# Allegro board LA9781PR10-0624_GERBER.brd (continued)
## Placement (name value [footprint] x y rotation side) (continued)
R775  -  [R_0402]  226.97 72.45 0 bottom
R779  -  [R_0402]  247.06 65.34 180 bottom
R781  -  [R_0402]  41.57 68.66 180 top
R782  -  [R_0402]  238.73 61.48 270 bottom
R783  -  [R_0402]  21.61 166.69 0 top
R793  -  [R_0402]  246.15 69.66 0 bottom
R794  -  [R_0402]  233.78 61.48 270 bottom
R795  -  [R_0402]  236.7 61.48 270 bottom
R796  -  [R_0402]  27.76 23.1 270 top
R797  -  [R0402_0OHM]  226.97 73.34 0 bottom
R799  -  [R_0402]  35.48 84.77 180 bottom
R800  -  [R_0402]  237.72 80.53 270 bottom
R801  -  [R_0603]  289.47 133.29 0 top
R802  -  [R0402_0OHM]  244.96 60.57 90 bottom
R803  -  [R_0402]  238.61 79.62 90 bottom
R804  -  [R_0402]  244.07 61.48 270 bottom
R805  -  [R_0402]  232.38 78.25 270 bottom
R806  -  [R0402_0OHM]  98.2 37.91 0 top
R807  -  [R_0402]  233.27 78.25 270 bottom
R808  -  [R_0402]  63.14 57.86 0 bottom
R809  -  [R_0402]  271.63 69.48 270 bottom
R810  -  [R_0402]  236.19 37.1 270 bottom
R811  -  [R_0402]  236.19 34.94 270 bottom
R812  -  [R_0402]  252.02 45.02 180 bottom
R814  -  [R_0402]  254.3 45.91 180 bottom
R815  -  [R_0402]  104.42 165.27 180 top
R816  -  [R_0402]  293.6 61.23 270 bottom
R817  -  [R_0402]  240 57.29 270 bottom
R819  -  [R_0402]  236.4 38.47 90 bottom
R822  -  [R_0402]  234.47 44.77 0 bottom
R823  -  [R_0402]  128.24 170.04 90 bottom
R824  -  [R_0402]  129.54 157.34 270 bottom
R825  -  [R_0402]  234.29 39.38 270 bottom
R827  -  [R0402_0OHM]  4.04 144.89 90 bottom
R828  -  [R0402_0OHM]  4.93 144.89 90 bottom
R829  -  [R_0402]  233.09 44.77 180 bottom
R830  -  [R0402_0OHM]  275.64 75.5 180 bottom
R831  -  [R0402_0OHM]  275.64 74.61 180 bottom
R834  -  [R0402_0OHM]  237.34 55 270 bottom
R835  -  [R_0402]  247.55 37.33 90 bottom
R836  -  [R_0402]  245.72 38.24 270 bottom
R837  -  [R_0402]  238.23 55 270 bottom
R838  -  [R_0402]  234.48 42.36 0 bottom
R839  -  [R0402_0OHM]  104.42 164.39 180 top
R840  -  [R_0402]  2.04 150.18 90 bottom
R841  -  [R_0402]  233.09 42.36 180 bottom
R842  -  [R0402_0OHM]  6.32 144.89 90 bottom
R843  -  [R_0402]  253.52 50.86 0 bottom
R844  -  [R0402_0OHM]  7.21 144.89 90 bottom
R845  -  [R0402_0OHM]  244.83 37.33 90 bottom
R846  -  [R0402_0OHM]  232.05 51.5 0 bottom
R847  -  [R_0402]  272.9 30.54 0 bottom
R848  -  [R_0402]  270.89 30.29 180 bottom
R849  -  [R_0402]  272.9 28.51 0 bottom
R850  -  [R_0402]  272.9 29.53 0 bottom
R851  -  [R_0402]  3.41 150.19 90 bottom
R852  -  [R_0402]  3.41 149.29 270 bottom
R853  -  [R_0402]  2.04 149.29 270 bottom
R858  -  [R_0402]  272.9 34.61 0 bottom
R859  -  [R_0402]  272.9 33.59 0 bottom
R860  -  [R_0402]  272.9 32.58 0 bottom
R861  -  [R_0402]  272.9 31.56 0 bottom
R864  -  [R_0402]  272.9 35.62 0 bottom
R866  -  [R0402_0OHM]  250.98 39.18 0 bottom
R869  -  [R_0402]  251.89 46.93 180 bottom
R870  -  [R_0402]  243.05 34.79 90 bottom
R871  -  [R_0402]  234.47 45.66 0 bottom
R872  -  [R_0402]  233.21 36.18 90 bottom
R874  -  [R_0402]  241.27 35.7 270 bottom
R875  -  [R_0402]  233.09 45.66 180 bottom
R876  -  [R_0402]  242.16 35.7 270 bottom
R877  -  [R_0402]  98.19 40.7 0 top
R878  -  [R0402_0OHM]  98.19 39.82 0 top
R879  -  [R_0402]  234.16 36.18 90 bottom
R880  -  [R_0402]  234.47 40.5 0 bottom
R884  -  [R_0402]  233.09 41.42 180 bottom
R885  -  [R_0402]  246.68 55.44 180 bottom
R887  -  [R_0402]  245.72 35.7 270 bottom
R889  -  [R_0402]  251.76 50.86 180 bottom
R892  -  [R_0402]  253.39 46.93 0 bottom
R893  -  [R_0402]  255.67 50.86 0 bottom
R895  -  [R_0402]  114.73 61.41 180 bottom
R897  -  [R_0402]  101.65 59.37 180 bottom
R899  -  [R_0402]  101.65 66.61 180 bottom
R900  -  [R_0402]  101.65 56.71 180 bottom
R901  -  [R_0402]  101.65 63.95 180 bottom
R904  -  [R_0402]  294.99 109.08 90 bottom
R909  -  [R_0402]  38.45 72.5 90 top
R925  -  [R_0402]  46.96 75.17 90 top
R930  -  [R_0402]  40.99 76.09 270 top
R931  -  [R_0402]  44.68 75.17 90 top
R932  -  [R_0402]  35.46 87.06 0 top
R933  -  [R_0402]  39.6 76.09 270 top
R934  -  [R_0402]  26.26 85.23 270 top
R935  -  [R_0402]  25.88 130.44 270 top
R936  -  [R_0402]  114.73 62.29 180 bottom
R937  -  [R_0402]  129.77 168.03 270 top
R938  -  [R_0402]  290.84 103.39 90 bottom
R939  -  [R_0402]  133.75 169.99 0 top
R940  -  [R_0402]  13.36 134.05 0 top
R941  -  [R_0402]  291.86 104.31 270 bottom
R942  -  [R_0402]  22.66 76.52 180 top
R943  -  [R_0402]  29.01 82.74 180 top
R944  -  [R_0402]  15.2 134.18 0 top
R952  -  [R_0402]  256.69 39.94 0 bottom
R955  -  [R_0402]  284.83 88.66 270 top
R956  -  [R_0402]  284.83 89.52 90 top
R1068  -  [R0402_0OHM]  238.3 37.91 180 bottom
R1069  -  [R_0402]  243.13 57.34 180 bottom
R1118  -  [R_0402]  247.5 35.7 270 bottom
R1121  -  [R_0402]  91.41 155.84 270 bottom
R1122  -  [R_0402]  87.1 148.91 90 top
R1123  -  [R_0402]  92.3 155.84 270 bottom
R1124  -  [R_0402]  88.17 152.59 180 top
R1125  -  [R_0402]  232.38 38.47 90 bottom
R1126  -  [R_0402]  252.02 42.74 180 bottom
R1128  -  [R_0402]  42.01 163.31 90 top
R1133  -  [R_0402]  297.45 112.42 0 bottom
R1134  -  [R_0402]  297.46 111.52 0 bottom
R1137  -  [R_0402]  95.86 167.96 270 bottom
R1138  -  [R_0402]  98.98 160.72 180 bottom
R1139  -  [R_0402]  105.76 162.95 270 bottom
R1140  -  [R_0402]  94.33 165.27 180 top
R1144  -  [R0402_0OHM]  117.07 93.61 270 top
R1164  -  [R_0402]  41.12 163.31 90 top
R1165  -  [R_0402]  38.45 164.22 270 top
R1167  -  [R_0402]  66.6 160.47 180 bottom
R1170  -  [R_0402]  66.6 161.35 180 bottom
R1171  -  [R_0402]  43.97 162.24 0 bottom
R1179  -  [R_0402]  252.02 44.13 180 bottom
R1180  -  [R0402_0OHM]  253.59 43.55 90 bottom
R1181  -  [R_0402]  229.58 46.5 180 bottom
R1197  -  [R_0402]  246.61 35.7 270 bottom
R1207  -  [R_0402]  275.64 76.52 180 bottom
R1530  -  [R_0402]  74.78 112.15 270 bottom
R1532  -  [R_0402]  69.44 107.94 90 bottom
R1537  -  [R_0402]  70.33 114.31 270 bottom
R1539  -  [R_0402]  71.22 109.46 90 bottom
R1611  -  [R_0402]  42.9 75.17 90 top
R1613  -  [R_0402]  281.52 84.2 90 bottom
R1614  -  [R_0402]  280.63 85.12 270 bottom
R1621  -  [R_0402]  98.2 38.8 0 top
R1622  -  [R_0402]  59.1 53.79 180 bottom
R1623  -  [R_0402]  61.24 56.82 0 bottom
R1624  -  [R_0402]  56.35 55.18 0 bottom
R1626  -  [R0402_0OHM]  277.14 82.49 0 bottom
R1630  -  [R_0402]  56.29 59.12 0 bottom
R1633  -  [R_0402]  58.19 52.9 0 bottom
R1635  -  [R_0402]  203.73 52.11 90 bottom
R1636  -  [R_0402]  80.39 36.07 270 top
R1643  -  [R0402_0OHM]  178.97 35.88 0 top
R1644  -  [R0402_0OHM]  178.97 36.77 0 top
R1645  -  [R0402_0OHM]  178.97 38.67 0 top
R1646  -  [R0402_0OHM]  178.97 37.78 0 top
R1970  -  [R0402_0OHM]  45.29 133.46 90 top
R1971  -  [R_0402]  46.2 133.46 90 top
R1972  -  [R_0402]  41.5 147.05 90 top
R1977  -  [R_0402]  42.39 147.97 270 top
R1978  -  [R_0402]  79.73 148.73 270 top
R1979  -  [R_0402]  100.33 141.75 90 bottom
R1980  -  [R_0402]  251.76 51.88 180 bottom
R1981  -  [R_0402]  251.76 36.89 180 bottom
R1984  -  [R_0402]  249.48 34.86 180 bottom
R1985  -  [R0402_0OHM]  242.16 37.33 90 bottom
R1986  -  [R_0402]  249.53 37.33 90 bottom
R1989  -  [R0402_0OHM]  124.94 141.97 90 top
R1990  -  [R_0402]  150.85 158.38 270 top
R1991  -  [R_0402]  149.96 157.47 90 top
R1992  -  [R_0402]  151.74 158.38 270 top
R1993  -  [R_0402]  152.63 157.47 90 top
R1994  -  [R_0402]  133.45 147.89 270 bottom
R1995  -  [R_0402]  133.45 146.11 270 bottom
R1996  -  [R0402_0OHM]  144.12 152.51 90 top
R2151  -  [R_0402]  19.53 153.18 270 top
R2152  -  [R_0402]  17.88 153.18 270 top
R2153  -  [R_0402]  20.42 153.18 270 top
R2154  -  [R_0402]  17.12 147.46 270 top
R2157  -  [R_0402]  23.42 148.4 180 top
R2158  -  [R_0402]  231.88 60.57 90 bottom
R2159  -  [R_0402]  20.67 144.77 90 top
R2160  -  [R_0402]  92.05 131.05 90 bottom
R2164  -  [R_0402]  82.78 113.4 90 bottom
R2165  -  [R_0402]  83.67 113.4 90 bottom
R2166  -  [R_0402]  84.68 113.4 90 bottom
R2167  -  [R_0402]  85.57 113.4 90 bottom
R2168  -  [R_0402]  86.59 113.4 90 bottom
R2169  -  [R_0402]  87.48 113.4 90 bottom
R2170  -  [R_0402]  88.49 113.4 90 bottom
R2171  -  [R_0402]  89.38 113.4 90 bottom
R2172  -  [R_0402]  82.9 131.05 90 bottom
R2173  -  [R_0402]  83.79 131.05 90 bottom
R2174  -  [R_0402]  84.81 131.05 90 bottom
R2175  -  [R_0402]  85.7 131.05 90 bottom
R2176  -  [R_0402]  86.71 131.05 90 bottom
R2177  -  [R_0402]  87.6 131.05 90 bottom
R2178  -  [R_0402]  88.62 131.05 90 bottom
R2179  -  [R_0402]  89.51 131.05 90 bottom
R2180  -  [R_0402]  8.66 145.23 0 top
R2181  -  [R_0402]  8.66 144.21 0 top
R2182  -  [R_0402]  15.54 142.81 180 top
R2183  -  [R_0402]  15.54 143.7 180 top
R2184  -  [R_0402]  14.63 146.37 0 top
R2185  -  [R_0402]  14.63 145.48 0 top
R2186  -  [R_0402]  12.85 146.37 0 top
R2187  -  [R_0402]  15.54 144.59 180 top
R2188  -  [R0402_0OHM]  247.42 64.45 0 bottom
R2190  -  [R_0402]  285.98 59.17 90 bottom
R2191  -  [R_0402]  287.25 65.55 270 bottom
R2192  -  [R_0402]  289.33 65.55 270 bottom
R2193  -  [R_0402]  288.26 59.17 90 bottom
R2194  -  [R_0402]  247.42 63.56 0 bottom
R2195  -  [R_0402]  246.16 66.24 0 bottom
R2198  -  [R_0402]  132.13 146.11 180 bottom
R2199  -  [R_0402]  132.13 147 180 bottom
R2200  -  [R_0402]  265.96 76.39 0 bottom
R2201  -  [R_0402]  272.13 78.47 90 bottom
R3664  -  [R_0402]  114.73 66.87 180 bottom
R3665  -  [R_0402]  114.73 60.52 180 bottom
R3666  -  [R_0402]  100.73 61.15 0 bottom
R3667  -  [R_0402]  114.73 59.63 180 bottom
R3668  -  [R_0402]  100.73 68.39 0 bottom
R3669  -  [R_0402]  101.65 67.5 180 bottom
R3670  -  [R_0402]  101.65 60.26 180 bottom
RC1  -  [R_0402]  168.09 126.19 90 bottom
RC2  -  [R_0402]  168.09 125.33 270 bottom
RC4  -  [R_0603]  202.47 143.96 0 top
RC5  -  [R_0402]  201.78 146.44 270 top
RC6  -  [R_0402]  212.7 120 90 top
RC8  -  [R_0402]  212.7 126.51 270 top
RC9  -  [R_0402]  209.7 122.37 0 bottom
RC10  -  [R_0402]  206.6 147.71 270 top
RC11  -  [R_0402]  208.38 147.71 270 top
RC13  -  [R0402_0OHM]  157.02 125.03 180 bottom
RC14  -  [R_0402]  202.49 105.98 180 top
RC15  -  [R0402_0OHM]  157.02 125.92 180 bottom
RC16  -  [R_0402]  201.57 106.87 0 top
RC17  -  [R_0402]  207.49 146.8 90 top
RC18  -  [R_0402]  203 103.44 180 top
RC19  -  [R_0402]  202.67 150.51 270 bottom
RC20  -  [R_0402]  204.27 107.76 180 top
RC21  -  [R_0402]  205.21 121.1 0 top
RC22  -  [R0402_0OHM]  157.02 128.21 180 bottom
RC23  -  [R_0402]  203.86 126.68 0 bottom
RC24  -  [R_0402]  198.73 149.59 90 bottom
RC25  -  [R0402_0OHM]  200.91 145.94 270 top
RC26  -  [R0402_0OHM]  202.67 148.22 270 bottom
RC27  -  [R_0402]  201.65 148.22 270 bottom
RC28  -  [R0402_0OHM]  201.57 108.65 0 top
RC29  -  [R_0402]  204.77 125.79 180 bottom
RC32  -  [R_0402]  204.77 124.91 180 bottom
RC35  -  [R_0402]  198.73 148.22 270 bottom
RC40  -  [R_0402]  204.77 128.46 180 bottom
RC41  -  [R_0402]  199.74 150.51 270 bottom
RC42  -  [R_0402]  196.44 100.22 270 bottom
RC43  -  [R0402_0OHM]  157.02 127.06 180 bottom
RC44  -  [R_0402]  203.94 149.24 270 bottom
RC45  -  [R_0402]  169.14 146.42 90 bottom
RC46  -  [R_0402]  201.57 107.76 0 top
RC47  -  [R_0402]  203.86 103.44 0 top
RC49  -  [R_0402]  195.43 100.22 270 bottom
RC51  -  [R0402_0OHM]  156.77 130.37 180 bottom
RC52  -  [R0402_0OHM]  156.77 129.48 180 bottom
RC53  -  [R0402_0OHM]  200.68 131.76 0 top
RC54  -  [R_0402]  200.68 132.65 0 top
RC55  -  [R_0402]  197.46 100.22 270 bottom
RC56  -  [R_0402]  199.74 147.31 90 bottom
RC57  -  [R_0402]  203.94 147.46 270 bottom
RC58  -  [R_0402]  202.21 133.67 0 top
RC59  -  [R_0402]  168.12 130.44 270 bottom
RC60  -  [R_0402]  201.6 137.22 180 top
RC61  -  [R_0402]  201.6 136.34 180 top
RC62  -  [R_0402]  205.26 116.4 0 top
RC63  -  [R_0402]  201.6 135.45 180 top
RC65  -  [R_0402]  167.28 146.5 0 bottom
RC66  -  [R_0402]  199.74 148.22 270 top
RC67  -  [R0402_0OHM]  199.74 144.89 90 top
RC68  -  [R0402_0OHM]  198.86 144.89 90 top
RC69  -  [R_0402]  156.11 124.14 0 bottom
RC70  -  [R_0402]  198.86 147.31 90 top
RC71  -  [R_0402]  157.02 123.25 180 bottom
RC72  -  [R_0402]  163.55 100.36 270 bottom
RC73  -  [R_0402]  164.44 99.41 90 bottom
RC75  -  [R_0402]  165.12 152.72 0 bottom
RC76  -  [R_0402]  201.95 123.38 0 top
RC77  -  [R_0402]  201.95 124.91 0 top
RC78  -  [R_0402]  203.86 129.35 0 bottom
RC80  -  [R_0402]  201.65 149.59 90 bottom
RC81  -  [R_0402]  203.86 124.02 0 bottom
RC83  -  [R_0402]  209.57 126.94 0 bottom
RC85  -  [R_0402]  210.49 126.05 180 bottom
RC86  -  [R_0402]  203.86 117.67 0 bottom
RC88  -  [R_0402]  205.76 103.44 0 top
RC89  -  [R_0402]  207.16 105.22 0 top
RC99  -  [R_0603]  202.47 142.69 0 top
RC101  -  [R_0402]  203.6 109.67 0 top
RC103  -  [R0402_0OHM]  204.52 110.55 180 top
RC104  -  [R_0402]  204.52 111.44 180 top
RC105  -  [R0603_0OHM]  155.99 125.54 0 top
RC106  -  [R_0603]  157.31 126.81 180 top
RC109  -  [R_0402]  173.07 46.62 270 top
RC110  -  [R_0402]  143.66 84.65 0 top
RC111  -  [R_0402]  166.98 45.23 270 top
RC124  -  [R_0402]  212.7 122.82 270 top
RC126  -  [R_0402]  202.67 148.22 270 top
RC128  -  [R_0402]  200.63 148.22 270 bottom
RC129  -  [R0402_0OHM]  202.67 146.44 270 top
RC130  -  [R_0402]  200.89 147.31 90 top
RD1  -  [R0402_0OHM]  197.88 68.99 180 top
RD2  -  [R_0402]  197.88 69.88 180 top
RD5  -  [R_0402]  208.2 93.54 180 top
RD6  -  [R0402_0OHM]  207.29 91.76 0 top
RD7  -  [R0402_0OHM]  148.31 77.2 90 top
RD8  -  [R0402_0OHM]  125.32 80.4 270 top
RD9  -  [R0402_0OHM]  169.53 46.72 0 top
RD10  -  [R0402_0OHM]  148.07 83.6 0 top
RD11  -  [R0402_0OHM]  169.78 42.91 180 top
RD13  -  [R0402_0OHM]  126.21 78.5 270 top
RD14  -  [R0402_0OHM]  196.77 62.93 180 bottom
RD15  -  [R_0402]  196.77 62.04 180 bottom
RD16  -  [R0402_0OHM]  146.53 77.2 90 bottom
RD19  -  [R0402_0OHM]  116.61 59.25 0 bottom
RD20  -  [R0402_0OHM]  116.61 60.76 0 bottom
RD23  -  [R0402_0OHM]  197.76 61.6 180 top
RD24  -  [R_0402]  197.76 64.26 180 top
RD25  -  [R0402_0OHM]  144.5 45.86 270 top
RD26  -  [R0402_0OHM]  116.25 56.96 180 top
RD27  -  [R0402_0OHM]  116.25 56.07 180 top
RD30  -  [R_0402]  209.07 91.76 0 top
RD32  -  [R0402_0OHM]  184.25 46.37 0 bottom
RD33  -  [R_0402]  186.03 45.45 90 bottom
RD34  -  [R0402_0OHM]  146.53 45.86 270 bottom
RD36  -  [R0402_0OHM]  129.39 46.11 270 bottom
RD37  -  [R0402_0OHM]  131.42 45.2 90 bottom
RD41  -  [R_0402]  172.11 44.77 0 top
RD42  -  [R_0402]  98.2 37.02 0 top
RD43  -  [R_0402]  173.89 44.77 0 top
RD44  -  [R_0402]  172.11 43.75 0 top
RD45  -  [R_0402]  147.42 80.4 270 top
RD46  -  [R_0402]  146.53 79.49 90 top
RD47  -  [R_0402]  148.82 80.4 270 top
RD48  -  [R_0402]  167.99 42.94 270 top
RD49  -  [R_0402]  166.98 42.02 90 top
RD50  -  [R_0402]  165.96 42.94 270 top
RD51  -  [R0402_0OHM]  208.2 92.65 180 top
RE1  -  [R_0402]  100.76 65.72 180 bottom
RE2  -  [R_0402]  101.65 58.48 180 bottom
RE5  -  [R_0402]  248.33 60.64 180 bottom
RE11  -  [R_0402]  104.75 114.31 270 bottom
RE12  -  [R_0402]  101.7 114.31 270 bottom
RH3  -  [R_0402]  40.28 76.65 0 bottom
RH4  -  [R_0402]  40.28 77.53 0 bottom
RH5  -  [R_0402]  69.87 50.61 0 top
RH6  -  [R_0402]  40.28 78.42 0 bottom
RH7  -  [R_0402]  40.28 79.31 0 bottom
RH8  -  [R_0402]  40.28 80.2 0 bottom
RH9  -  [R_0402]  40.28 81.09 0 bottom
RH10  -  [R_0402]  40.28 82.87 0 bottom
RH11  -  [R_0402]  53.39 77.03 180 bottom
RH12  -  [R_0402]  59.74 77.15 180 bottom
RH13  -  [R_0402]  53.39 77.92 180 bottom
RH14  -  [R_0402]  53.39 78.93 180 bottom
RH16  -  [R_0402]  53.39 81.47 180 bottom
RH17  -  [R_0402]  40.28 81.98 0 bottom
RH18  -  [R_0402]  70.79 49.72 180 top
RH19  -  [R_0402]  59.99 73.34 180 bottom
RH20  -  [R_0402]  60.04 72.66 180 top
RH22  -  [R_0402]  60.04 73.6 180 top
RH24  -  [R_0402]  59.99 65.34 180 top
RH25  -  [R_0402]  58.22 75.25 180 bottom
RH26  -  [R_0402]  40.28 83.76 0 bottom
RH27  -  [R_0402]  53.39 85.92 180 bottom
RH28  -  [R_0402]  40.28 84.65 0 bottom
RH30  -  [R_0402]  40.28 87.44 0 bottom
RH31  -  [R_0402]  40.28 88.33 0 bottom
RH32  -  [R_0402]  52.55 87.69 0 bottom
RH34  -  [R_0402]  61.24 77.15 0 top
RH35  -  [R_0402]  78.97 51.12 90 bottom
RH36  -  [R_0402]  62.28 76.77 180 bottom
RH37  -  [R_0402]  62.28 77.66 180 bottom
RH38  -  [R0402_0OHM]  65.89 54.98 90 top
RH39  -  [R_0402]  65.89 57.14 90 top
RH40  -  [R_0402]  78.97 49.09 180 top
RH41  -  [R_0402]  76.17 51.12 90 bottom
RH42  -  [R_0402]  67.66 54.04 90 top
RH43  -  [R_0402]  71.22 54.17 90 bottom
RH44  -  [R_0402]  66.78 54.04 90 top
RH45  -  [R_0402]  79.98 48.83 90 bottom
RH46  -  [R_0603]  56.04 69.41 0 bottom
RH47  -  [R_0402]  57.58 67.88 180 bottom
RH48  -  [R_0402]  59.08 69.15 0 bottom
RH50  -  [R_0402]  59.08 70.3 0 bottom
RH51  -  [R0402_0OHM]  69.7 77.99 270 top
RH52  -  [R_0402]  59.08 68.14 0 bottom
RH53  -  [R0402_0OHM]  64.99 59 0 top
RH54  -  [R_0402]  62.28 69.41 180 bottom
RH55  -  [R_0402]  62.28 70.42 180 bottom
RH56  -  [R_0402]  62.28 68.52 180 bottom
RH57  -  [R_0402]  70.59 77.08 90 top
RH59  -  [R_0402]  78.97 48.83 90 bottom
RH60  -  [R_0402]  77.06 51.12 90 bottom
RH61  -  [R_0402]  75.41 49.26 90 bottom
RH63  -  [R_0402]  77.95 51.12 90 bottom
RH65  -  [R_0402]  79.98 53.66 90 bottom
RH66  -  [R0402_0OHM]  62.51 83.63 0 bottom
RH67  -  [R_0402]  70.33 51.85 90 bottom
RH70  -  [R_0402]  68.1 85.28 0 bottom
RH73  -  [R_0402]  59.08 64.33 0 top
RH75  -  [R_0402]  58.95 59.75 0 top
RH76  -  [R_0402]  62.33 75.88 180 top
RH77  -  [R_0402]  76.3 46.34 90 top
RH78  -  [R_0402]  58.95 61.66 0 top
RH79  -  [R_0402]  62.3 60.08 180 bottom
RH80  -  [R_0402]  70.79 54.14 90 top
RH81  -  [R_0402]  70.33 54.17 90 bottom
RH82  -  [R0402_0OHM]  90.13 65.47 0 bottom
RH83  -  [R_0402]  75.41 46.34 90 top
RH84  -  [R_0402]  61.44 62.52 0 bottom
RH85  -  [R_0402]  56.79 67.37 0 top
RH86  -  [R_0402]  73.63 46.34 90 top
RH87  -  [R_0402]  64.74 49.85 270 top
RH88  -  [R_0402]  58.95 62.55 0 top
RH89  -  [R_0402]  61.39 58.33 0 bottom
RH90  -  [R_0402]  63.14 77.15 0 top
RH91  -  [R_0402]  61.36 60.14 0 top
RH92  -  [R0402_0OHM]  90.13 64.58 0 bottom
RH93  -  [R_0402]  69.01 84.27 180 bottom
RH94  -  [R_0402]  88.62 66.61 180 top
RH95  -  [R_0402]  88.62 65.6 180 top
RH96  -  [R0402_0OHM]  91.49 80.33 180 bottom
RH97  -  [R_0402]  86.71 66.49 270 top
RH98  -  [R0402_0OHM]  73.33 77.28 180 top
RH99  -  [R_0402]  91.49 79.31 180 bottom
RH100  -  [R_0402]  72.41 76.26 0 top
RH101  -  [R0402_0OHM]  61.36 59.25 0 top
RH102  -  [R0402_0OHM]  59.08 67.37 0 top
RH103  -  [R0402_0OHM]  56.79 66.49 0 top
RH104  -  [R0402_0OHM]  63.47 59.63 0 bottom
RH105  -  [R0402_0OHM]  62.3 59.21 180 bottom
RH106  -  [R0402_0OHM]  58.95 63.44 0 top
RH107  -  [R_0402]  206.17 122.49 180 top
RH108  -  [R_0402]  212.7 124.6 270 top
RH109  -  [R0402_0OHM]  56.68 80.15 270 top
RH110  -  [R0402_0OHM]  55.79 80.15 270 top
RH111  -  [R0402_0OHM]  58.46 80.15 270 top
RH112  -  [R_0402]  58.95 57.87 0 top
RH113  -  [R_0402]  88.75 52.08 270 top
RH114  -  [R0402_0OHM]  57.57 80.15 270 top
RH115  -  [R_0402]  91.04 61.02 180 bottom
RH116  -  [R_0402]  91.04 62.04 180 bottom
RH117  -  [R_0402]  91.04 63.06 180 bottom
RH118  -  [R_0402]  88.82 64.58 180 top
RH119  -  [R_0402]  72.11 55.06 270 bottom
RH120  -  [R_0402]  61.42 73.6 0 top
RH121  -  [R0402_0OHM]  92.67 66.87 0 bottom
RH122  -  [R0402_0OHM]  92.67 65.98 0 bottom
RH123  -  [R_0402]  59.99 66.36 180 top
RH124  -  [R_0402]  62.28 68.64 180 top
RH125  -  [R_0402]  59.99 66.61 180 bottom
RH126  -  [R0402_0OHM]  115.54 170.96 270 bottom
RH127  -  [R0402_0OHM]  114.65 170.96 270 bottom
RH128  -  [R_0402]  62.28 69.53 180 top
RH130  -  [R_0402]  61.37 65.09 0 bottom
RH132  -  [R_0402]  89.64 51.17 90 top
RH133  -  [R0402_0OHM]  90.13 68.01 0 bottom
RH135  -  [R0402_0OHM]  90.13 67.12 0 bottom
RH137  -  [R0402_0OHM]  92.67 69.28 0 bottom
RH139  -  [R0402_0OHM]  92.67 68.39 0 bottom
RH140  -  [R_0402]  62.28 66.23 180 bottom
RH142  -  [R0402_0OHM]  92.67 70.93 0 bottom
RH144  -  [R0402_0OHM]  92.67 71.82 0 bottom
RH145  -  [R_0402]  60.04 71.69 180 top
RH146  -  [R_0402]  90.27 58.61 0 bottom
RH147  -  [R_0402]  62.28 67.5 180 bottom
RH148  -  [R_0402]  73.89 54.17 90 bottom
RH150  -  [R_0402]  81.57 58.69 270 top
RH151  -  [R_0402]  82.46 58.69 270 top
RH152  -  [R0402_0OHM]  92.62 73.87 90 bottom
RH153  -  [R_0402]  91.71 72.97 0 bottom
RH154  -  [R0402_0OHM]  90.13 69.66 0 bottom
RH155  -  [R_0402]  93.5 57.9 180 bottom
RH156  -  [R0402_0OHM]  90.13 70.55 0 bottom
RH157  -  [R_0402]  87.1 55.94 180 top
RH158  -  [R_0402]  86.26 59.63 0 top
RH159  -  [R_0402]  87.1 54.93 180 top
RH160  -  [R_0402]  86.26 60.64 0 top
RH161  -  [R_0402]  87.1 57.09 180 top
RH162  -  [R_0402]  86.21 58.36 0 top
RH163  -  [R0402_0OHM]  87.1 72.2 90 top
RH164  -  [R_0402]  90.27 56.58 0 bottom
RH165  -  [R_0402]  90.14 74.36 0 bottom
RH166  -  [R_0402]  58.95 58.87 0 top
RH167  -  [R_0402]  62.28 82.23 180 bottom
RH168  -  [R_0402]  68.6 81.29 270 top
RH169  -  [R_0402]  62.28 81.34 180 bottom
RH170  -  [R_0402]  61.36 62.17 0 top
RH171  -  [R_0402]  71.68 54.14 90 top
RH174  -  [R_0402]  53.87 66.99 0 top
RH175  -  [R_0402]  53.87 66.1 0 top
RH176  -  [R_0402]  87.81 82.49 180 bottom
RH177  -  [R_0402]  113.84 54.29 180 bottom
RH178  -  [R_0402]  112.06 54.29 180 bottom
RH179  -  [R_0402]  110.29 54.29 180 bottom
RH180  -  [R_0402]  113.82 65.98 0 bottom
RH181  -  [R_0402]  108.51 54.29 180 bottom
RH182  -  [R_0402]  106.73 54.29 180 bottom
RH183  -  [R_0402]  104.95 54.29 180 bottom
RH184  -  [R_0402]  103.17 54.29 180 bottom
RH185  -  [R_0402]  100.48 54.29 0 bottom
RH186  -  [R_0402]  113.82 58.74 0 bottom
RH187  -  [R_0402]  76.99 61.85 270 top
RH188  -  [R0402_0OHM]  80.62 81.42 270 bottom
RH189  -  [R0402_0OHM]  61.62 63.69 0 bottom
RH190  -  [R0402_0OHM]  53.77 67.5 180 bottom
RH191  -  [R0402_0OHM]  62.61 61.15 180 bottom
RH192  -  [R_0402]  80.36 78.63 270 top
RH195  -  [R0402_0OHM]  65.76 78.5 270 top
RH200  -  [R_0402]  61.36 73.47 0 bottom
RH206  -  [R_0402]  61.36 79.57 0 bottom
RH208  -  [R_0402]  59.99 75.25 180 bottom
RH210  -  [R_0402]  62.28 65.22 180 top
RH211  -  [R_0402]  62.28 66.36 180 top
RH212  -  [R_0402]  74.52 47.26 270 top
RH213  -  [R_0402]  62.28 64.33 180 top
RH214  -  [R_0402]  66.83 80.38 90 top
RH215  -  [R_0402]  67.71 80.38 90 top
RH216  -  [R_0402]  73.25 50.56 270 top
RH217  -  [R_0402]  71.73 50.61 270 top
RH218  -  [R_0402]  65.87 80.38 90 top
RH219  -  [R0402_0OHM]  61.36 80.46 0 bottom
RH222  -  [R_0402]  62.28 67.63 180 top
RH223  -  [R_0402]  59.99 68.26 180 top
RH224  -  [R_0402]  59.08 74.36 0 bottom
RH225  -  [R_0402]  59.99 72.33 180 bottom
RH226  -  [R_0402]  62.28 74.49 180 bottom
RH227  -  [R_0402]  62.28 72.45 180 bottom
RH228  -  [R_0402]  59.99 76.26 180 bottom
RH229  -  [R_0402]  62.28 71.44 180 bottom
RH230  -  [R_0402]  62.33 75.76 180 bottom
RH231  -  [R_0402]  59.99 71.31 180 bottom
RH232  -  [R_0402]  67.54 65.72 0 top
RH234  -  [R_0402]  74.65 66.64 90 top
RH236  -  [R_0603]  83.03 75.95 90 top
RH237  -  [R_0603]  73.76 50.98 270 bottom
RH238  -  [R0603_0OHM]  72.49 50.98 270 bottom
RH239  -  [R_0402]  86.84 67.63 180 top
RH240  -  [R_0603]  66.65 46.48 90 top
RH241  -  [R0603_0OHM]  93.45 76.45 90 bottom
RH242  -  [R0805_0OHM]  79.35 51.88 180 top
RH243  -  [R_0805]  79.35 53.66 180 top
RH244  -  [R0805_0OHM]  89.6 69.53 180 top
RH245  -  [R_0805]  77.99 58.1 0 top
RH246  -  [R0603_0OHM]  65.38 46.48 90 top
RH254  -  [R_0402]  65.84 64.96 180 top
RH258  -  [R0402_0OHM]  61.36 61.02 0 top
RH259  -  [R0402_0OHM]  58.95 60.77 0 top
RH307  -  [R0402_0OHM]  92.67 63.31 0 bottom
RH308  -  [R0402_0OHM]  92.67 64.2 0 bottom
RH328  -  [R_0402]  87.43 51.88 180 top
RP1  -  [RP_0804_8P4R]  229.78 74.24 0 bottom
RP2  -  [RP_0804_8P4R]  250.1 69.65 180 bottom
RP3  -  [RP_0804_8P4R]  241.39 59.94 90 bottom
RP4  -  [RP_0804_8P4R]  241.39 77.72 90 bottom
RP5  -  [RP_0804_8P4R]  250.94 35.31 270 bottom
RP6  -  [RP_0804_8P4R]  252.64 49.58 180 bottom
RP7  -  [RP_0804_8P4R]  242.17 55.63 270 bottom
RP8  -  [RP_0804_8P4R]  230.04 64.06 180 bottom
RPH1  -  [RP_0804_8P4R]  78.95 46.87 270 top
RPH3  -  [RP_0804_8P4R]  76.95 81.02 90 top
RPH5  -  [RP_0804_8P4R]  55.47 61.79 0 bottom
RPH6  -  [RP_0804_8P4R]  59.79 65.47 180 bottom
RPH7  -  [RP_0804_8P4R]  59.92 62.35 180 bottom
RPH8  -  [RP_0804_8P4R]  70.98 45.21 90 top
RPH9  -  [RP_0804_8P4R]  68.06 45.21 90 top
RPH10  -  [RP_0804_8P4R]  63.15 79.81 0 top
SW1  -  [SW_SKRBAAE010_4P]  299.39 155.76 0 top
T57  -  [TPC12]  64.64 78.21 270 bottom
T58  -  [TPC12]  68.25 76.14 270 top
T59  -  [TPC12]  78.36 55.39 90 bottom
T60  -  [TPC12]  183.59 114.82 180 bottom
T61  -  [TPC12]  75.16 167.7 0 top
T64  -  [TPC12]  189.38 116.07 180 bottom
T65  -  [TPC12]  73.91 74.66 270 top
T66  -  [TPC12]  89.46 80.42 90 bottom
T67  -  [TPC12]  73.86 73.36 270 top
T68  -  [TPC12]  69.44 65.77 270 top
T69  -  [TPC12]  174.6 130.66 180 bottom
T70  -  [TPC12]  200.47 104.38 0 top
T71  -  [TPC12]  200.51 105.73 0 top
T72  -  [TPC12]  185.56 114.9 180 bottom
T73  -  [TPC12]  157.59 135.5 0 top
T74  -  [TPC12]  157.58 137.35 0 top
T75  -  [TPC12]  180.41 130.65 180 bottom
T76  -  [TPC12]  179.51 129.72 180 bottom
T77  -  [TPC12]  171.68 130.62 180 bottom
T78  -  [TPC12]  159.07 122.67 180 bottom
T79  -  [TPC12]  190.59 128.84 180 bottom
T80  -  [TPC12]  191.46 124.51 180 bottom
T81  -  [TPC12]  155.88 135.98 0 top
T82  -  [TPC12]  156.6 139.07 0 top
T83  -  [TPC12]  177.52 129.82 180 bottom
T84  -  [TPC12]  175.6 129.64 180 bottom
T85  -  [TPC12]  191.5 127.33 180 bottom
T86  -  [TPC12]  156.91 120.21 180 bottom
T87  -  [TPC12]  167.82 128.46 180 bottom
T88  -  [TPC12]  169.2 128.8 180 bottom
T89  -  [TPC12]  191.46 123.17 180 bottom
T90  -  [TPC12]  200.8 121.69 0 top
T91  -  [TPC12]  202.82 146.28 180 bottom
T92  -  [TPC12]  191.4 121.83 180 bottom
T93  -  [TPC12]  162.41 100.39 180 bottom
T94  -  [TPC12]  165.58 100.39 180 bottom
T95  -  [TPC12]  201.14 98.49 180 bottom
T96  -  [TPC12]  158.52 119.71 180 bottom
T97  -  [TPC12]  174.47 115.76 180 bottom
T98  -  [TPC12]  177.54 114.87 180 bottom
T99  -  [TPC12]  200.56 102.5 0 top
T100  -  [TPC12]  160.6 100.27 180 bottom
T101  -  [TPC12]  159.23 121.29 180 bottom
T102  -  [TPC12]  156.74 118.75 180 bottom
T103  -  [TPC12]  200.89 123.38 0 top
T104  -  [TPC12]  206.46 114.9 180 bottom
T105  -  [TPC12]  200.89 124.91 0 top
T106  -  [TPC12]  208.46 127.22 180 bottom
T107  -  [TPC12]  210.49 124.68 180 bottom
T108  -  [TPC12]  202.79 117.79 180 bottom
T109  -  [TPC12]  207.75 116.52 180 bottom
T110  -  [TPC12]  170.53 129.82 180 bottom
T111  -  [TPC12]  200.82 119.9 0 top
T112  -  [TPC12]  176.43 130.65 180 bottom
T113  -  [TPC12]  178.54 130.62 180 bottom
T114  -  [TPC12]  189.65 129.77 180 bottom
T115  -  [TPC12]  174.53 128.8 180 bottom
T116  -  [TPC12]  203.55 114.87 180 bottom
T117  -  [TPC12]  200.89 126.29 0 top
T118  -  [TPC12]  67.54 55.13 270 bottom
T119  -  [TPC12]  203.3 116.52 180 bottom
T120  -  [TPC12]  84.87 81.33 90 bottom
T121  -  [TPC12]  86.14 80.26 90 bottom
T122  -  [TPC12]  82.12 63.54 270 top
T123  -  [TPC12]  82.38 61.93 270 top
T124  -  [TPC12]  80.58 79.6 90 bottom
T125  -  [TPC12]  79.5 75.73 0 top
T126  -  [TPC12]  64.65 76.89 90 bottom
T127  -  [TPC12]  204.91 116.51 180 bottom
T128  -  [TPC12]  202.55 127.61 0 top
T129  -  [TPC12]  66.39 74.49 270 top
T130  -  [TPC12]  89.66 82.45 270 bottom
T131  -  [TPC12]  88.48 81.94 270 bottom
T132  -  [TPC12]  88.54 81.34 90 bottom
T133  -  [TPC12]  87.7 81.57 90 bottom
T134  -  [TPC12]  90.7 81.61 270 bottom
T135  -  [TPC12]  206.35 116.52 180 bottom
T136  -  [TPC12]  200.89 133.67 0 top
T137  -  [TPC12]  205.1 113.6 180 bottom
T138  -  [TPC12]  206.51 113.55 180 bottom
T139  -  [TPC12]  200.87 128.52 0 top
T140  -  [TPC12]  204.95 114.87 180 bottom
T141  -  [TPC12]  68.35 68.05 270 top
T142  -  [TPC12]  107.22 91.38 90 top
T143  -  [TPC12]  107.42 89.98 90 top
T144  -  [TPC12]  71.28 66.47 270 top
T145  -  [TPC12]  65.89 55.31 90 bottom
T146  -  [TPC12]  17.51 121.07 270 top
T147  -  [TPC12]  83.79 68.01 270 top
T148  -  [TPC12]  83.89 67.39 270 top
T149  -  [TPC12]  86.89 81.43 270 bottom
T150  -  [TPC12]  86.27 81.6 270 bottom
T151  -  [TPC12]  191.17 125.84 180 bottom
T152  -  [TPC12]  190.65 130.68 180 bottom
T153  -  [TPC12]  158.9 118.42 180 bottom
T154  -  [TPC12]  190.35 117.67 180 bottom
T155  -  [TPC12]  232.04 53.4 180 bottom
T156  -  [TAIMA_IH-115-F_24P]  57.89 147.65 180 bottom
T157  -  [TPC12]  200.63 141.75 0 top
T158  -  [TPC12]  201.4 143.19 0 top
T159  -  [TPC12]  190.85 120.46 180 bottom
T160  -  [TPC12]  181.58 129.78 180 bottom
T161  -  [TPC12]  256.64 52.52 180 bottom
T162  -  [TPC12]  200.8 144.11 180 bottom
T163  -  [TPC12]  191.68 129.74 180 bottom
T164  -  [TPC12]  230.22 72.07 180 bottom
T165  -  [TPC12]  244.96 76.26 180 bottom
T166  -  [TPC12]  238.52 62.61 180 bottom
T167  -  [TPC12]  203.17 123.05 180 bottom
T168  -  [TPC12]  204.99 147.16 180 bottom
T169  -  [TPC12]  204.63 121.63 180 bottom
T170  -  [TPC12]  202.91 127.36 180 bottom
T171  -  [TPC12]  203.15 121.63 180 bottom
T172  -  [TPC12]  203.19 120.27 180 bottom
T173  -  [TPC12]  204.68 122.94 180 bottom
T174  -  [TPC12]  204.66 120.29 180 bottom
T175  -  [TPC12]  49.85 147.74 0 top
T176  -  [TPC12]  51.69 134.84 0 top
U2  -  [SLG55594AVTR_TDFN8_2X2]  278.24 86.06 0 bottom
U3  -  [TC7SH125FU_SSOP5]  104.64 165.87 180 bottom
U5  -  [AP2330W-7_SC59-3]  44.73 165.93 90 bottom
U6  -  [AP2330W-7_SC59-3]  92.99 166.56 90 bottom
U9  -  [PS8339BQFN56GTR2-A0_QFN56_7X7]  32.28 151.64 90 top
U10  -  [TC7SH08FU_SSOP5]  41.74 103.88 0 bottom
U11  -  [TS3DV20812RHHR_VQFN36_6X6]  89.28 148.43 90 bottom
U12  -  [TC7SH08FU_SSOP5]  60.23 56.97 270 bottom
U13  -  [TS3DV20812RHHR_VQFN36_6X6]  80.52 152.06 0 bottom
U14  -  [SN74AHC1G08DCKR_SC70-5]  119.72 133.28 0 top
U15  -  [TC7SH08FU_SSOP5]  106.46 94.41 90 top
U16  -  [74AHC1G09GW_TSSOP5]  109.56 127.18 0 top
U17  -  [74AHC1G09GW_TSSOP5]  112.48 127.18 0 top
U18  -  [RT9818A-44GU3_SC70-3]  58.21 58.87 270 bottom
U19  -  [MAX14885EETLLFT_TQFN40_5X5]  97.51 103.06 180 bottom
U20  -  [PI3C3125LEX_TSSOP14]  54.92 105.24 0 top
U22  -  [PS8330BQFN48GTR-A0_QFN48_7X7]  281.7 71.54 90 bottom
U23  -  [RTD2136S-VE-CG_QFN48_6X6]  126.9 147.3 270 bottom
U25  -  [SN74AHC1G08DCKR_SC70-5]  117.05 133.28 0 top
U26  -  [PS8520CTQFN20GTR2-A_TQFN20_4X4]  181.97 36.28 90 bottom
U27  -  [SN74AHC1G08DCKR_SC70-5]  122.39 133.28 0 top
U28  -  [APL3512ABI-TRG_SOT23-5]  95.5 167.35 270 top
U29  -  [EMC4021-1-EZK-TR_QFN32_5X5]  36.65 90.55 180 bottom
U30  -  [AP2337SA-7_SOT23-3]  287.79 136.17 270 top
U31  -  [WGI217LM-QPN9-A2_QFN48_6X6]  114.71 89.69 90 top
U32  -  [PI3L720ZHEX_TQFN42_9X3P5]  107.1 101.08 0 top
U33  -  [APL3512ABI-TRG_SOT23-5]  113.85 168.41 90 top
U34  -  [TPS22965DSGR_SON8_2X2]  109.82 173 180 top
U35  -  [TPS22965DSGR_SON8_2X2]  38.75 129.85 270 top
U36  -  [TPS22966DPUR_SON14_2X3]  73.37 40.03 180 top
U37  -  [TPS22966DPUR_SON14_2X3]  55.21 15.37 90 bottom
U39  -  [AT97SC3204-X2A18-AB_TSSOP28]  256.11 65.25 270 bottom
U40  -  [TPS22966DPUR_SON14_2X3]  100.73 40.44 270 top
U42  -  [TPS22965DSGR_SON8_2X2]  102.23 166.53 0 top
U43  -  [TPS22965DSGR_SON8_2X2]  273.9 38.08 180 bottom
U44  -  [PS8513CTQFN20GTR2-A_TQFN20_4X4]  4.69 147.52 0 top
U45  -  [TPS2560DRCR_SON10_3X3]  297.52 62.09 180 bottom
U46  -  [ECE5048-LZY_DQFN132_11X11]  243.68 73.16 270 bottom
U48  -  [TPS2560DRCR-PG1P1_SON10_3X3]  18.79 161.91 0 top
U49  -  [TPS22965DSGR_SON8_2X2]  14.06 142.47 180 bottom
U50  -  [TC7SH08FU_SSOP5]  238.29 57.86 270 bottom
U51  -  [MEC5075-LZY_DQFN132_11X11]  237.6 42.42 90 bottom
U52  -  [W25Q64FVSSIQ_SO8]  110.91 69.41 270 bottom
U53  -  [W25Q32FVSSIQ_SO8]  110.91 62.29 270 bottom
U54  -  [TC7SH08FU_SSOP5]  104.64 162.69 180 bottom
U55  -  [TC7SH08FU_SSOP5]  96.76 160.91 180 bottom
U57  -  [TPS22965DSGR_SON8_2X2]  30.16 32.08 90 top
U58  -  [TC7SH08FU_SSOP5]  30.27 88.47 270 top
U59  -  [INA199A2DCKR_SC70-6]  6.18 138.64 270 bottom
U60  -  [INA219AIDCNRG4_SOT23-8]  10.86 145.18 270 top
U63  -  [TPS22965DSGR_SON8_2X2]  100.95 73.89 0 top
U88  -  [LNG3DMTR_LGA16_3X3]  175.76 40.49 0 top
U625  -  [PS8713BTQFN24GTR2_TQFN24_4X4]  269.61 76.47 0 bottom
U629  -  [PS8331BQFN60GTR-A0_QFN60_5X9]  38.4 123.88 270 bottom
UC1  -  [SN74LVC1G07DCKR_SC70-5]  209.28 150.79 180 top
UC2  -  [74AHC1G09GW_TSSOP5]  205.72 104.57 90 top
UC3  -  [74AHC1G09GW_TSSOP5]  66.51 84.92 270 bottom
UH1  -  [DH82LPMS-QC4C-A1_FCBGA_695P]  67.81 58.44 0 bottom
UH2  -  [NL17SZ08DFT2G_SC70-5]  63.62 51.18 180 top
UH3  -  [TC7SH08FU_SSOP5]  57.52 77.72 180 top
Y3  -  [Y_X3G025000DI1H-H_4P]  121.09 92.94 90 top
Y6  -  [Y_Q13FC1350000_2P]  240.11 34.99 180 bottom
YH1  -  [Y_Q13FC1350000_2P]  63.47 55.33 90 top
YH2  -  [Y_Q22FA2380049900_4P]  95.11 75.07 0 bottom

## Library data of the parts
C1 C3 C328 C332 = C_0603: room: MXM
C2 = C_0805: room: MXM
C4 C7 C8 C90 C92 C94-C96 = C_0402: room: MXM
C5 C498 = C_0805: room: HDD
C12-C15 C18-C23 C1181 = C_0402: room: CRT
C24 C395 C403 C404 C406-C409 C415 C419 C420 = C_0402: room: HDD
C25 C56 C292 C343 C417 C476 C477 C773 CC138 CD92 PC199 PC735 PC736 PC744 PC746 PC783 PC1080 PC1081 = C_0402
C45 C48 C550-C553 CE3 = C_0402: room: TPM
C46 C1337 C1339 C1340 = C_0402: room: HDMI
C47 = C_0805: room: HDMI
C51 C54 C55 PC105 PC106 PC216 PC217 PC219 PC220 PC402 PC406 PC407 PC703 PC729 PC730 = C_0402: room: ETY-ROOM
C86 C402 C405 C410 C437 C495 C499 C504 = C_0402: room: DP/HDMI MUX
C87 C88 C313 C496 C497 = C_0402: room: DP
C97 C494 = C_0402: room: DP/HDMI DEMUX
C100 C101 C103-C105 C107 C108 C110-C112 C114 C116-C118 = C_0402: room: TRANSLATOR
C106 C109 C113 C115 = C_0603: room: TRANSLATOR
C243 C248 C298 C726 C727 C1183-C1186 C1188 = C_0402: room: LVDS
C244 C305 C545 = C_0402: room: EDP
C249 C296 C546 = C_0603: room: LVDS
C250 = C_0603: room: EDP
C270 C272-C274 C277 C287 C288 C291 C294 C319 C320 C327 C339 C340 C364 C370 C1179 C1343 C1346 C1350 C1351 = C_0402: room: THERMAL
C279-C286 C295 C302-C304 C306-C309 C397 C398 = C_0402: room: DP; signal model: C_0402NEW
C289 C290 = C_0402: room: RSMRST
C297 = C_1206: room: LVDS
C299 C301 C310 C311 = C_0402: room: CAM
C300 = C_0805: room: CAM
C323 C324 = C_APXK2R5ARA331MF451: room: USB3.0
C329 C330 = C_0805: room: THERMAL
C356 = C_0805: room: +5V_MXM SOURCE
C359 C1174 C1332 C1341 = C_0402: room: DP_SW
C362 C449 = C_0603: room: +3V_MXM SOURCE
C366-C369 C424-C427 C431 C438-C444 C697-C700 = C_0402: room: DOCKING; signal model: C_0402NEW
C371-C380 = C_0402: room: EDP; signal model: C_0402NEW
C383-C386 C389 C390 C393 C394 C418 C421-C423 = C_0402: room: HDD; signal model: C_0402NEW
C387 C388 = C_0402: room: DP_SW; signal model: C_0402NEW
C391 = C_0402: room: FFS
C392 = C_0603: room: FFS
C396 C400 C416 C475 C772 PC701 PC734 PC745 PC786 PC791 PC792 PC1099 = C_0603
C411-C414 = C_0402: room: HDD; signal model: C_0402NEW_C_0402NEW
C428 C429 = C_0402: room: ODD
C430 C432-C434 = C_0402: room: ODD; signal model: C_0402NEW_C_0402NEW
C435 C538 = C_0402: room: +3.3V_M_SOURCE
C436 = C_0402: room: +5V_MXM SOURCE
C445-C448 = C_0402: room: FLASH; signal model: C_0402NEW_C_0402NEW
C450 C453 C670 = C_0402: room: USB3.0
C452 C454 C456 C457 C465 C487-C489 = C_0402: room: USB3.0; signal model: C_0402NEW
C458-C461 = C_0402: room: LAN; signal model: C_0402NEW_C_0402NEW
C462 C464 C770 = C_0603: room: LAN
C463 C466-C474 C478 C547 = C_0402: room: LAN
C479-C481 C484 C486 = C_0603: room: LOM
C482 = C_0805: room: DP
C483 C1167 = C_0402: room: LOM
C485 = C_1808: room: LOM
C505-C512 = C_0402: room: DP/HDMI MUX; signal model: C_0402NEW
C513 = C_0603: room: +3.3V_ALW_PCH SOURCE
C514 = C_0805: room: +5V_RUN SOURCE
C515-C534 = C_0402: room: DP/HDMI DEMUX; signal model: C_0402NEW
C536 = C_0603: room: +3.3V_RUN_SOURCE
C539 = C_0402: room: +3.3V_SUS SOURCE
C540 C608 = C_0603: room: WLAN
C541 C610-C612 C614 = C_0402: room: WWAN
C542 C617 C618 C621 C623 = C_0402: room: FLASH
C543 C624 C634 C637-C639 = C_0402: room: WPAN
C544 = C_0402: room: +5VMOD SOURCE
C595 C601 C603-C607 = C_0402: room: WLAN
C596 C598 = C_0402: room: WLAN; signal model: C_0402NEW_C_0402NEW
C597 C599 = C_0402: room: WWAN; signal model: C_0402NEW_C_0402NEW
C613 = C_0805: room: WWAN
C615 = C_APXK2R5ARA331MF451: room: WWAN
C616 C628-C631 C643 = C_0402: room: SIM
C619 = C_V: room: FLASH
C622 = C_0805: room: FLASH
C626 C636 = C_0402: room: WPAN; signal model: C_0402NEW_C_0402NEW
C633 = C_0603: room: WPAN
C645 = C_0603: room: SIM
C661 C662 C668 C675 = C_0402: room: ESATA
C663-C666 C671-C674 C677-C680 = C_0402: room: ESATA; signal model: C_0402NEW_C_0402NEW
C667 = C_D2: room: ESATA
C669 = C_0805: room: USB3.0
C676 = C_0805: room: ESATA
C695 C696 C701 C704 CE8 CE9 = C_0402: room: DOCKING
C702 C703 = C_0603: room: DOCKING
C708-C710 C712 C713 C716-C719 = C_0402: room: SIO
C714 = C_0603: room: SIO
C715 = C_0402: room: USB
C720 C733-C737 C739-C744 C747 C757 C777 C780 C781 C1345 C1348 C1349 C1352-C1355 = C_0402: room: KBC
C721-C725 C763 = C_0402: room: IO
C746 C1216 CE1 CE2 = C_0402: room: FLASH ROM
C748 C753 C754 = C_0402: room: BT
C756 C758 = C_0402: room: KB
C759 = C_0402: room: PWR SW
C762 = C_0603: room: WWAN
C764 = C_0603: room: FLASH
C766 = C_0603: room: DP/HDMI MUX
C767 = C_0603: room: +5VMOD SOURCE
C774 = C_0402: room: MXM_PWR_SRC SOURCE
C776 = C_1206: room: MXM_PWR_SRC SOURCE
C778 = C_0402: room: LED
C779 C782 = C_0603: room: KBC
C783 = C_0603: room: DP/HDMI DEMUX
C793 C794 = C_0603: room: USB3.0
C1145 C1146 C1149 C1159 = C_0402: room: LVDS SW
C1176 = C_D2E: room: WWAN
C1177 = C_0805: room: LAN
C1178 = C_0805: room: +3.3V_LAN SOURCE
C1182 = C_0603: room: CRT
C1333-C1336 C1338 = C_0402: room: HDMI; signal model: C_0402NEW
CC1-CC32 CC44-CC64 CC67-CC77 = C_0402: room: CPU; signal model: C_0402NEW
CC33-CC43 CC78 CC79 CC161-CC166 CC168-CC171 PC900-PC904 PC909-PC914 PC917-PC926 PC935-PC943 = C_0805: room: CPU
CC65 CC66 = C_0402: room: XDP1
CC137 = C_0603: room: CPU
CC140 CC156 = C_0402: room: CPU
CC167 CC172 = C_D2: room: CPU
CD1-CD6 CD15-CD28 CD37-CD50 CD59-CD72 CD81-CD91 = C_0402: room: MEMORY
CD7-CD13 CD29-CD35 CD51-CD57 CD73-CD79 = C_0603: room: MEMORY
CD14 CD36 CD58 CD80 = C_SX: room: MEMORY
CE6 = C_0805: room: DOCKING
CH2 = C_0402: room: XDP2
CH4-CH7 CH9-CH19 CH22-CH25 CH27 CH29 CH30 CH34-CH37 CH39 CH40 CH42-CH51 CH53-CH59 CH64-CH83 = C_0402: room: PCH
CH20 CH21 CH26 CH31-CH33 CH38 CH41 CH52 CH63 = C_0603: room: PCH
CH28 = C_0805: room: PCH
CH60 = C_SX
CMOS1 ME1 = SHORTPADS: User Part Number: PART#; room: PCH
D6 = BAT54CW_SOT323-3: room: LVDS
D7 D8 D18 D19 = RB751VM-40TE-17_SOD323-2: room: MXM
D14 D16 = TVWDF1004AD0_DFN9: room: USB3.0
D15 D17 = L30ESDL5V0C3-2_SOT23-3: room: USB
D28 = RB751S40T1_SOD523-2: room: BT
D31 D35 D36 = RB751V40_SC76-2: room: WLAN
D32 = RB751S40T1_SOD523-2: room: DOCKING
D33 = L30ESD24VC3-2_SOT23-3: room: DOCKING
D53 D64 D66 D68 D69 D71 = RB751VM-40TE-17_SOD323-2: room: LVDS
D59 D62 = RB751S40T1_SOD523-2: room: LED
D65 = RB751V40_SC76-2: room: LVDS
D73 = L30ESDL5V0C3-2_SOT23-3: room: ESATA
D90 = RB751S40T1_SOD523-2: room: THERMAL
D91 = BAT1000-7-F_SOT23-3
F3 = F_1206L150THWR
FD1-FD4 = FIDUCIAL_C40M80: room: LED
H1 H3 H5 H6 H8-H11 H16 H18 H20 H21 H25 = H_3P0: room: LED
H2 H7 = H_3P8: room: LED
H4 = H_12P0X7P5: room: LED
H12-H15 = H_4P2: room: LED
H17 H19 H23 H24 = H_3P6: room: LED
H22 = H_3P6X3P0: room: LED
H26 = H_1P2: room: LED
H27 H28 = H_1P2
JAPS1 = TYCO_1-2041070-6_16P: room: APS
JBT1 = ACES_50228-0127N-001_12P: room: BT
JCAM1 = ACES_50238-0207N-002_20P: room: CAM
JCPU1 = INTEL_HASWELL_947P-T: room: CPU
JCRT1 = SUYIN_070449HR015M221ZR_15P: room: CRT
JDEG2 = ACES_87152-10071_10P: room: KBC
JDIMM1 = TYCO_2-2013310-1_204P: room: MEMORY
JDIMM2 JDIMM3 = TYCO_2-2013289-1_204P: room: MEMORY
JDIMM4 = TYCO_2-2013290-1_204P: room: MEMORY
JDOCK1 = JAE_WD2F144WB5R400_144P: room: DOCKING
JDP1 = FOX_3V11211-NBYD7-7H_20P: room: DP
JEDP1 = ACES_50398-04071-001_40P: room: EDP
JESA1 = TAIWI_EU093-117CRL-TW_11P: room: ESATA
JFAN1 JFAN2 = ACES_50271-0040N-001_4P: room: THERMAL
JHDMI1 = CONCR_099AAAC19BBLCNF_19P: room: HDMI
JIO1 = FOX_QTSA1401-7011-9H_140P-T: room: IO
JKB1 = E-T_6900K-G10N-40R_10P: room: KB
JLOM1 = SANTA_130454-H_13P: room: LOM
JLVDS1 = ACES_50398-04071-001_40P: room: LVDS
JMINI1 = LCN_DAN08-52526-0100_52P: room: WWAN
JMINI2 = LCN_DAN08-52526-0100_52P: room: WLAN
JMINI3 = LCN_DAN08-52526-0100_52P: room: WPAN
JMINI4 = LCN_DAN08-52526-0100_52P: room: FLASH
JMXM1 = JAE_MM70-314-310B1-1-R3_310P-S: room: MXM
JODD1 = OCTEK_SLS-13SZAB_13P: room: ODD
JPB1 = ACES_50228-0067N-001_6P: room: PWR SW
JRTC1 = ACES_50271-0020N-001_2P: room: ETY-ROOM
JSATA1 JSATA2 = OCTEK_SAT-22PDAB_22P: room: HDD
JSIM1 = T-SOL_159-1000302602_10P-T: room: SIM
JSPI1 = TYCO_2-2041070-0_20P-T: room: FLASH ROM
JTAG1 = SHORTPADS: User Part Number: PART#; room: KBC
JUSB1 JUSB2 = LOTES_AUSB0041-P002A_9P: room: USB3.0
JUSH1 = E-T_6700K-Y20N-00L_20P: room: USH
JWL1 = ACES_50228-0034N-001_3P: room: ETY-ROOM
JXDP1 = ACES_50559-02601-001_26P-T: room: XDP1
JXDP2 = SAMTE_BSH-030-01-L-D-A_60P: room: XDP2
L1-L3 = MURAT_BLM15BB470SN1D_2P: room: CRT
L4 L5 = MURAT_BLM15AG121SN1D_L0402_2P: room: CRT
L10 L11 = MURAT_DLW21SN121SQ2L_4P: room: CAM
L19 L23-L25 = MURAT_DLW21SN900HQ2L_0805_4P: room: HDMI
L29 = TAIYO_CBC2012T4R7M_2P: room: LAN
L39 = MURAT_DLW21SN900SQ2L_0805_4P: room: USB
L40 L42-L44 = MURAT_DLW21SN900HQ2L_0805_4P: room: USB3.0
L41 = CHENG_OCE2012120YZF_4P: room: USB
L51 = MURAT_DLW21SN900SQ2L_0805_4P: room: ESATA
L60 L61 = KC_FBMA-L11-201209-221LMA30_2P: room: TRANSLATOR
L62 = CYNTE_PG031B-4R7MS_2P: room: TRANSLATOR
L63-L70 = DELTA_0603CS-120EJTS_2P
LH1 = MURAT_BLM18PG181SN1D_2P: room: PCH
LH2 = MURAT_LQM18FN4R7M00D_2P
PBATT1 = SUYIN_200045GR009M28QZR_9P: room: ETY-ROOM
PC1 = C_EEEFK1E101YP: room: DCIN_DETECTOR
PC2 PC9 PC15 = C_0603: room: P_DCIN
PC4 PC5 PC11 = C_0402: room: P_DCIN
PC6 PC17-PC21 = C_0402: room: MONITOR PWR_SRC_MXM
PC7 PC8 PC511 = C_0603: room: VSB
PC14 = C_0805: room: P_DCIN
PC16 = C_0402: room: VSB
PC30 PC104 PC109 PC110 PC202 PC203 PC502-PC504 PC512-PC514 PC533-PC535 PC707 PC708 = C_0805: room: CPU_CORE
PC31 PC700 PC706 PC1004 = C_0603: room: CHARGER
PC101 PC102 = C_APXK6R3ARA221MF451: room: 3V5V
PC111 PC112 PC114 PC116-PC120 PC501 PC521 PC540 = C_0603: room: ETY-ROOM
PC201 = C_APXK2R5ARA331MF451: room: VGA_CORE
PC204 PC205 PC209 PC211 PC214 PC215 = C_0402: room: 1.5V/0.75V
PC206 PC210 PC212 PC213 = C_0603: room: 1.5V/0.75V
PC207 PC208 = C_0805: room: 1.5V/0.75V
PC301 = C_APXK2R5ARA331MF451: room: ETY-ROOM
PC302 PC303 PC307 PC309 = C_0402: room: 1.05V
PC304 PC305 = C_0805: room: 1.05V
PC306 PC308 = C_0603: room: 1.05V
PC400 PC403 PC404 = C_0805: room: ETY-ROOM
PC500 PC507 PC508 PC519 PC523 PC532 PC538 PC545 = C_0603: room: CPU_CORE
PC509 PC515 PC516 PC520 PC522 PC528 PC539 PC541-PC544 PC546 PC547 = C_0402: room: CPU_CORE
PC510 PC525-PC527 = C_0402: room: DDR_VTT
PC529-PC531 = C_EEEFK1E101YP: room: CPU_CORE
PC702 PC704 PC705 PC717 PC727 PC728 PC731 PC732 = C_0402: room: CHARGER
PC715 PC718 PC719 = C_0805: room: CHARGER
PC733 = C_0402: room: P_SELECTOR
PC905 PC907 PC908 PC916 = C_D2: room: ETY-ROOM
PC906 PC915 = C_D2
PC1001 = C_0805: room: SELECTOR
PC1002 PC1003 PC1009 = C_0402: room: SELECTOR
PC1005-PC1008 = C_0603: room: SELECTOR
PD1 = BAS40CW_SOT323-3: room: ETY-ROOM
PD2 = TVNST52302AB0_SOT523-3: room: ETY-ROOM
PD3 = TVNST52302AB0_SOT523-3
PD5 = SDMK0340L-7-F_SOD323-2: room: ETY-ROOM
PD8 = D_0603: room: P_DCIN
PD700 = SBR3A40SA-13_SMA2: room: ETY-ROOM
PD701 = BAT54CW_SOT323-3: room: ETY-ROOM
PD703 PD1099 PD1100 = SDMK0340L-7-F_SOD323-2
PD1001 PD1002 = PDS5100H-13_POWERDI5-3: room: ETY-ROOM
PD1010 = BAT54CW_SOT323-3
PH500 PR21 PR23 PR100-PR102 PR104-PR106 PR112 PR119 PR400 PR402-PR405 PR517 PR523 PR531 PR541 PR543 PR732 PR734 PR736 PR737 PR744 PR745 PR749 PR1001 PR1003 PR1018 PR1028 = R_0402: room: ETY-ROOM
PH501 PR500 PR503 PR504 PR507 PR509 PR512 PR514 PR516 PR518 PR519 PR521 PR525 PR528 PR529 PR533 PR536 PR537 PR544-PR547 PR550 PR551 PR555-PR557 PR1013 PR1024 = R_0402: room: CPU_CORE
PJP3 = JUMP_43X79: room: +5VMOD SOURCE
PJP9 = JUMP_43X39: room: CODEC
PJP29 = JUMP_43X39: room: SIO
PJP30 = JUMP_43X79: room: USB3.0
PJP31 = JUMP_43X79: room: ESATA
PJP34 = JUMP_43X39: room: USB3.0
PJP65 = JUMP_43X39: room: KBC
PJP77 = JUMP_43X39: room: TPM
PJP78 PJP79 = JUMP_43X118: room: MXM_PWR_SRC SOURCE
PJP82 = JUMP_43X118: room: +5V_RUN SOURCE
PJP89-PJP94 = JUMP_43X79
PJP100-PJP103 = JUMP_43X118: room: 3V/5V
PJP200 = JUMP_43X118: room: 1.5V/0.75V
PJP201 = JUMP_43X39: room: 1.5V/0.75V
PJP202 = JUMP_43X39: room: VGA_CORE
PJP203 PJP204 = JUMP_43X118: room: ETY-ROOM
PJP300-PJP302 PJP400 PJP401 = JUMP_43X79: room: DDR_VTT_0.75V
PJPDC1 = ACES_50493-0110N-001_11P: room: ETY-ROOM
PL1 PL4 = CHT_C8BBPH853025_2P: room: ETY-ROOM
PL2 PL6 = TAIYO_FBMJ4516HS720NT_2P: room: P_DCIN
PL3 = MURAT_BLM15HG601SN1D_2P: room: P_DCIN
PL100 PL700 = CYNTE_PCMB053T-1R0MS_2P: room: ETY-ROOM
PL102 = TOKO_FDV0630-3R3M-P3_2P: room: VDDCI
PL103 = TOKO_FDSD0630-H-2R2M-P3_2P: room: ETY-ROOM
PL201 = CYNTE_PCMC104T-1R0MN_2P: room: 1.5V/0.75V
PL301 = TAI-T_VMPI0703AR-4R7M-Z01_2P: room: 1.05V
PL401 = CYNTE_PH041H-1R0MS_2P: room: ETY-ROOM
PL500-PL502 = NEC_MPC0740LR42C_2P: room: POWER/GPU
PL510 = L_1812-1806: room: CPU_CORE
PL701 = CYNTE_PCMB104T-5R6MS_2P: room: CHARGER
PQ1 = NTR4502PT1G_SOT23-3: room: P_DCIN
PQ2 = FDV301N_NL_SOT23-3: room: P_DCIN
PQ3 = MMST3904-7-F_SOT323-3: room: P_DCIN
PQ4 = TP0610K-T1-E3_SOT23-3: room: VSB
PQ5 PQ701 PQ1001 PQ1003 PQ1004 = SI7447DP_SO8_5P: room: ETY-ROOM
PQ7 = SSM3K7002FU_SC70-3: room: ETY-ROOM
PQ8 = IMD2AT-108_SC74-6: room: ETY-ROOM
PQ101 PQ102 PQ301 = SIS412DN-T1-GE3_POWERPAK8-5: room: ETY-ROOM
PQ103 PQ104 PQ303 = SI7716ADN-T1-GE3_POWERPAK8-5: room: ETY-ROOM
PQ201 PQ202 PQ704 = SIR472DP-T1-GE3_POWERPAK8-5: room: ETY-ROOM
PQ204 PQ205 PQ707 = DMN66D0LDW-7_SOT363-6: room: ETY-ROOM
PQ323 Q45 Q70 QC5 = DMN65D8LW-7_SOT323-3
PQ500 PQ502 PQ504 = CSD86350Q5D_SON8: room: ETY-ROOM
PQ501 PQ503 PQ505 = CSD86350Q5D_SON8
PQ700 PQ702 = NTR4502PT1G_SOT23-3: room: ETY-ROOM
PQ703 = NTGD4161PT1G_TSOP6: room: ETY-ROOM
PQ705 = FDMC7692S_MLP8-5: room: ETY-ROOM
PQ706 = DMN66D0LDW-7_SOT363-6: room: P_SELECTOR
PQ708 PQ1071 PQ1080 Q304 QD6 = DMN66D0LDW-7_SOT363-6
PQ1002 = SI4835DDY-T1-E3_SO8: room: ETY-ROOM
PQ1005 = SI4835DDY-T1-E3_SO8: room: MONITOR PWR_SRC_MXM
PQ1008 PQ1009 = SI7447DP_SO8_5P
PQ1010 PQ1011 PQ1082 = SSM3K7002FU_SC70-3
PQ1070 PQ1072 = NTR4502PT1G_SOT23-3
PQ1083 = IMD2AT-108_SC74-6
PR1 PR2 PR7-PR13 PR16 PR18 PR20 PR22 = R_0402: room: P_DCIN
PR3 = RP_0804_8P4R: room: ETY-ROOM
PR14 PR24 PR26-PR31 R14 = R_0402: room: MONITOR PWR_SRC_MXM
PR15 PR17 = R_0402: room: VSB
PR19 = R_0805: room: P_DCIN
PR25 = R_1206_4P-D: room: MONITOR PWR_SRC_MXM
PR33 PR103 PR111 PR406 PR501 PR522 PR524 PR526 PR700 PR703 PR714 PR739 PR742 = R0402_0OHM: room: ETY-ROOM
PR107 PR108 PR502 PR510 PR511 PR534 PR535 PR539 PR549 PR552 PR553 = R_0603: room: CPU_CORE
PR109 PR110 PR1005 = R_1206: room: ETY-ROOM
PR118 = R0402_0OHM: room: 3_5V
PR200 PR203 = R_0603: room: 1.5V/0.75V
PR201 PR204-PR208 = R_0402: room: 1.5V/0.75V
PR202 = R_1206: room: 1.5V/0.75V
PR209 = R_0402: room: 1P5V
PR211 PR213 PR216-PR225 = R_0402: room: GPU_CORE
PR240 PR315 = R0402_0OHM: room: VCCSA
PR300 PR302 PR303 PR305-PR307 = R_0402: room: 1.05V
PR301 = R_0603: room: 1.05V
PR304 = R_1206: room: 1.05V
PR401 = R_0603: room: P_1P8V
PR505 PR506 PR508 = R0402_0OHM: room: CPU_CORE; signal model: R_0402NEW
PR513 PR548 PR1002 PR1004 PR1006-PR1010 PR1012 PR1014-PR1017 PR1019-PR1023 PR1025 PR1027 PR1029 = R0402_0OHM: room: CPU_CORE
PR515 PR542 PR554 = R_1206: room: CPU_CORE
PR520 = R0603_0OHM: room: ETY-ROOM
PR558 PR704 PR706 PR708 PR713 PR715 PR716 PR757 PR758 PR760 PR762 PR764 PR771 PR772 PR1026 PR1030-PR1032 PR1071-PR1073 PR1081 PR1083 PR1097-PR1100 R43-R45 R49 R51 R83-R85 R90 R397 R400 R401 R426 R504 R727 R728 R757 R765 R799 R808 R840 R851-R853 R909 R925 R930 R931 R933 R944 R1139 R1140 R1181 R1611 R1635 R1636 R2180-R2187 R2195 RC47 RC72 RC73 RC89 RD5 RD30 RH113 RH132 RH150 RH151 RH167 RH169 RH218 RH328 = R_0402
PR701 PR723 = R_1206_4P-D: room: ETY-ROOM
PR702 PR705 PR718 PR763 PR766 PR1033 PR1070 R221 R433 R761 R846 R1970 RD6 RD9-RD11 RD51 RH219 = R0402_0OHM
PR707 PR717 PR735 PR738 PR740 PR741 PR743 PR746-PR748 = R_0402: room: CHARGER
PR709 PR712 = R_0402: room: ETY-ROOM; signal model: R_0402NEW_R_0402NEW
PR710 PR711 = R0402_0OHM: room: CHARGER
PR724 = R_1206: room: CHARGER
PR759 PR761 PR765 RH240 = R_0603
PR775 = R_1206
PR1011 = R_0805: room: CPU_CORE
PU1 = TS5A63157DCKR_SC70-6: room: P_DCIN
PU2 = LM393DR_SO8: room: MONITOR PWR_SRC_MXM
PU101 = TPS51225CRUKR_QFN20_3X3: room: ETY-ROOM
PU200 = RT8207MZQW_WQFN20_3X3: room: 1.5V/0.75V
PU300 = TPS51212DSCR_SON10_3X3: room: 1.05V
PU400 = SY8033BDBC_DFN10_3X3: room: ETY-ROOM
PU500 = ISL95812HRZ-T_QFN32_4X4: room: ETY-ROOM
PU501 = ISL6208BCRZ-T_QFN8_2X2: room: ETY-ROOM
PU700 = BQ24737RGRR_VQFN20_3P5X3P5: room: CHARGER
PU701 = INA199A1DCKR_SC70-6
PU703 = LM393DR_SO8: room: ETY-ROOM
PU704 UH3 = TC7SH08FU_SSOP5: room: PCH
PU1001 = CD3301RHHR_QFN36_6X6: room: ETY-ROOM
PU1080 PU1081 = TC7SH08FU_SSOP5
PWRSW1 = SHORTPADS: User Part Number: PART#; room: PWR SW
Q4 Q5 = DMN65D8LW-7_SOT323-3: room: MXM
Q14-Q17 Q26-Q28 = PMST3904_SOT323-3: room: THERMAL
Q21 = FDC654P-G_SSOT-6: room: LVDS
Q22 = DMN65D8LW-7_SOT323-3: room: LVDS
Q24 = DMG2301U-7_SOT23-3: room: CAM
Q29 = DMN66D0LDW-7_SOT363-6: room: FFS
Q47 Q52 = DMN65D8LW-7_SOT323-3: room: KBC
Q55 Q338 = DMN65D8LW-7_SOT323-3: room: USB
Q63 = SI4164DY-T1-GE3_SO8
Q74 Q84 Q318 = DMN66D0LDW-7_SOT363-6: room: LED
Q75 Q79 Q86 = PDTA114EU_SC70-3: room: LED
Q77 = DMN65D8LW-7_SOT323-3: room: WWAN
Q78 Q89 = DMN65D8LW-7_SOT323-3: room: WLAN
Q80 = PDTA114EU_SC70-3: room: NUM LED
Q81 = DMN66D0LDW-7_SOT363-6: room: ODD
Q87 = DMN65D8LW-7_SOT323-3: room: MXM_PWR_SRC SOURCE
Q90 = DMG2301U-7_SOT23-3: room: USB3.0
Q93 = DMN65D8LW-7_SOT323-3: room: NUM LED
Q110 Q113 Q335-Q337 Q339 Q340 Q343 Q347 = DMN66D0LDW-7_SOT363-6: room: DP_SW
Q115 = PMST3904_SOT323-3
Q124 = DMN66D0LDW-7_SOT363-6: room: WLAN
Q186 = SI4835DDY-T1-E3_SO8: room: MXM_PWR_SRC SOURCE
Q295 = DMN66D0LDW-7_SOT363-6: room: MXM
Q321 = DMN65D8LW-7_SOT323-3: room: LED
Q325 = DMN66D0LDW-7_SOT363-6: room: LAN
Q326 = DMN65D8LW-7_SOT323-3: room: DP/HDMI MUX
Q327 = L2N7002WT1G_SC-70-3: room: LAN
QC1 QD7 QD9 = L2N7002WT1G_SC-70-3
QC2 = DMN65D8LW-7_SOT323-3: room: CPU
QC6 = LBSS138LT1G_SOT23-3: room: CPU
QH3 = L2N7002WT1G_SC-70-3: room: PCH
